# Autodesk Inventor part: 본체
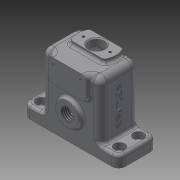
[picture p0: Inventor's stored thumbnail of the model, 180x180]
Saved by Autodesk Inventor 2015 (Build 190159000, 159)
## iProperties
Created: 2023-12
Part Number: 본체
Material: 일반
Document SubType Name: Modeling
Designer: user
Density: 1 g/cm^3
Appearance: 기본값
Author: user
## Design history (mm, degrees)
sketch "스케치1"
  geometry: L1 (-50, -20)-(50, -20); L2 (50, -20)-(50, 20); L3 (50, 20)-(-50, 20); L4 (-50, 20)-(-50, -20); L5 (-50, -20)-(50, 20); L6 (50, -20)-(-50, 20); 1 further point
  constraints: 12 end point, 2 midpoint, 2 parallel, 1 horizontal, 1 perpendicular
  dimensions: "d0" = 100 distance of L2.end L3.end; "d1" = 40 distance of L1.end L2.end
extrude "돌출1" new body sketch "스케치1" distance "d2" = 12; taper "d3" = 0 deg
sketch "스케치2"
  geometry: L1 (-31, -20)-(31, -20); L2 (31, -20)-(31, 20); L3 (31, 20)-(-31, 20); L4 (-31, 20)-(-31, -20); L5 (-31, -20)-(31, 20); L6 (31, -20)-(-31, 20); 1 further point
  constraints: 12 end point, 2 midpoint, 2 parallel, 1 horizontal, 1 perpendicular
  dimensions: "d4" = 62 distance of L2.end L3.end; "d5" = 40 distance of L1.end L2.end
extrude "돌출2" join sketch "스케치2" distance "d6" = 60; taper "d7" = 0 deg
sketch "스케치3"
  geometry: L1 (19, 72)-(81, 72) reference; L2 (30, 72)-(70, 72); L3 (70, 72)-(70, 48); L4 (70, 48)-(30, 48); L5 (30, 48)-(30, 72); 3 further points
  constraints: 8 end point, 2 coincident, 2 midpoint, 2 parallel, 1 horizontal, 1 perpendicular
  dimensions: "d8" = 40 distance of L2.start L2.end; "d9" = 24 distance of L2.end L3.end
extrude "돌출3" join sketch "스케치3" distance "d10" = 4; taper "d11" = 0 deg
sketch "스케치4"
  geometry: L1 (50, -20)-(-50, -20) reference; L2 (27, 16)-(-27, 16); L3 (-27, 16)-(-27, -16); L4 (-27, -16)-(27, -16); L5 (27, -16)-(27, 16); L6 (27, 16)-(-27, -16); L7 (-27, 16)-(27, -16); 1 further point
  constraints: 12 end point, 2 midpoint, 2 parallel, 1 horizontal, 1 perpendicular
  dimensions: "d12" = 4 distance between parallel lines of L1 L4; "d13" = 54 distance of L3.end L4.end
extrude "돌출4" cut sketch "스케치4" distance "d14" = 68; taper "d15" = 0 deg
sketch "스케치5"
  geometry: L1 (0, 0)-(100, 0) reference; C1 r 12 at (50, 28); 2 further points
  constraints: 1 centre point, 1 midpoint, 1 vertical alignment
  dimensions: "d16" = 28 distance of C1.centre point (50, 0); "d17" = 24 diameter of C1
extrude "돌출5" join sketch "스케치5" distance "d18" = 4; taper "d19" = 0 deg
fillet "모깎기1" dims "d26" = 7
fillet "모깎기2" dims "d27" = 7
node "작업 평면1"
sketch "스케치7"
  geometry: L1 (20, -24)-(-20, -24) reference; L2 (-17.321, 17)-(17.321, 17); L3 (-17.321, -3)-(17.321, -3); A1 r 20 centre (0, 7) between (-17.321, 17) and (-17.321, -3); A2 r 20 centre (0, 7) between (17.321, -3) and (17.321, 17); 1 further point
  constraints: 4 end point, 4 point on circle, 2 centre point, 1 horizontal, 1 parallel, 1 vertical alignment
  dimensions: "d30" = 31 distance from line of A1.centre L1; "d31" = 10 distance from line of L2 A1.centre; "d32" = 20 distance between parallel lines of L3 L2; "d33" = 20 radius of A1; "d34" = 20 radius of A2
extrude "돌출6" join sketch "스케치7" stored distance "d35" = 4; taper "d36" = 0 deg
sketch "스케치8"
  geometry: C1 r 8 at (0, 7); A1 r 20 centre (0, 7) between (17.321, -3) and (17.321, 17) reference; 1 further point
  constraints: 1 centre point, 1 coincident
  dimensions: "d37" = 16 diameter of C1
extrude "돌출7" cut sketch "스케치8" distance "d38" = 100; taper "d39" = 0 deg
chamfer "모따기1" distance "d40" = 1; stored, may be unused: second distance "d41" = 2, angle "d42" = 45 deg
sketch "스케치9"
  geometry: A1 r 20 centre (0, 7) between (-17.321, 17) and (-17.321, -3) reference; 2 further points
  constraints: 1 horizontal alignment
  dimensions: "d43" = 14 distance of point (-14, 7) A1.centre
hole "구멍1" sketch "스케치9" at (-14, 7) diameter "d44" = 2.459; stored, may be unused: countersink angle "d48" = 90 deg, drill point angle "d50" = 118 deg; dims "d45" = 6, "d46" = 4, "d47" = 2, "d49" = 8
fillet "모깎기3" dims "d51" = 7
sketch "스케치10"
  geometry: C1 r 12 at (24, 37) reference; C2 r 20 at (24, 37); 1 further point
  constraints: 1 centre point, 1 coincident
  dimensions: "d88" = 40 diameter of C2
extrude "돌출8" join sketch "스케치10" distance "d89" = 4; taper "d90" = 0 deg
hole "구멍6" diameter "d93" = 18; stored, may be unused: countersink angle "d97" = 90 deg, drill point angle "d99" = 118 deg; dims "d91" = 10, "d92" = 10, "d94" = 6, "d95" = 11, "d96" = 6.6, "d98" = 30
chamfer "모따기2" distance "d100" = 1; stored, may be unused: second distance "d101" = 2, angle "d102" = 45 deg
hole "구멍7" diameter "d105" = 13.835; stored, may be unused: countersink angle "d109" = 90 deg, drill point angle "d111" = 118 deg; dims "d103" = 10, "d104" = 10, "d106" = 32, "d107" = 11, "d108" = 6.6, "d110" = 25
sketch "스케치11"
  geometry: L1 (0, 0)-(0, -15); C1 r 10 at (0, 0) reference; 1 further point
  constraints: 2 end point, 1 vertical
  dimensions: "d112" = 15 distance of L1.start L1.end
hole "구멍8" sketch "스케치11" at (0, -15) diameter "d113" = 2.459; stored, may be unused: countersink angle "d117" = 90 deg, drill point angle "d119" = 118 deg; dims "d114" = 6, "d115" = 11, "d116" = 6.6, "d118" = 15
fillet "모깎기4" dims "d123" = 3
fillet "모깎기5" dims "d124" = 3
fillet "모깎기6" dims "d125" = 3
fillet "모깎기7" dims "d126" = 3
fillet "모깎기8" dims "d127" = 3
fillet "모깎기9" dims "d128" = 3
fillet "모깎기10" dims "d129" = 3
fillet "모깎기11" dims "d130" = 3
sketch "스케치12"
  geometry: 2 further points
  dimensions: "d131" = 10 vertical distance of point (-41, 10) point (0, 0); "d132" = 41 horizontal distance of point (-41, 10) point (0, 0)
hole "구멍9" sketch "스케치12" at (-41, 10) diameter "d133" = 6.6; stored, may be unused: countersink angle "d137" = 90 deg, drill point angle "d139" = 118 deg; dims "d134" = 6, "d135" = 11, "d136" = 6.6, "d138" = 15
fillet "모깎기12" dims "d140" = 3
fillet "모깎기13" dims "d141" = 3
fillet "모깎기14" dims "d142" = 5
fillet "모깎기15" dims "d143" = 3
fillet "모깎기16" dims "d144" = 5
sketch "스케치13"
  geometry: L1 (25, -11)-(49, -11) reference; L2 (65, 0)-(65, 26) reference; 2 further points
  constraints: 1 other
  dimensions: "d145" = 23 distance from line of point (25, 12) L1; "d146" = 40 distance from line of point (25, 12) L2
feature "엠보싱1" sketch "스케치13" dims "d147" = 0.5, "d148" = 0
sketch "스케치14"
  geometry: L1 (65, 72)-(35, 72) reference; 2 further points
  dimensions: "d149" = 6 distance from line of point (36, 66) L1; "d150" = 14 horizontal distance of point (36, 66) point (50, 0)
hole "구멍10" sketch "스케치14" at (36, 66) diameter "d151" = 2.459; stored, may be unused: countersink angle "d155" = 90 deg, drill point angle "d157" = 118 deg; dims "d152" = 6, "d153" = 11, "d154" = 6.6, "d156" = 15
node "솔리드1"
mirror "대칭1"
pattern_circular "원형 패턴1" dims angle "d121" = 360 deg
mirror "대칭2"
mirror "대칭3"
mirror "대칭4"
other parameters: "d28" = 4
